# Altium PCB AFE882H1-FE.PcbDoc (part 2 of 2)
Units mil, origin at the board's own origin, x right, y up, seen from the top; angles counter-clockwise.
Board outline 2755.91 x 1181.1 mil, 4 copper layers (Top Layer, Int1 (GND), Int2 (PWR), Bottom Layer), stack 53.912 mil thick; 80 components, 47 nets, 216 pads, 76 vias.
Unrouted connection lines stored in the file: 4.
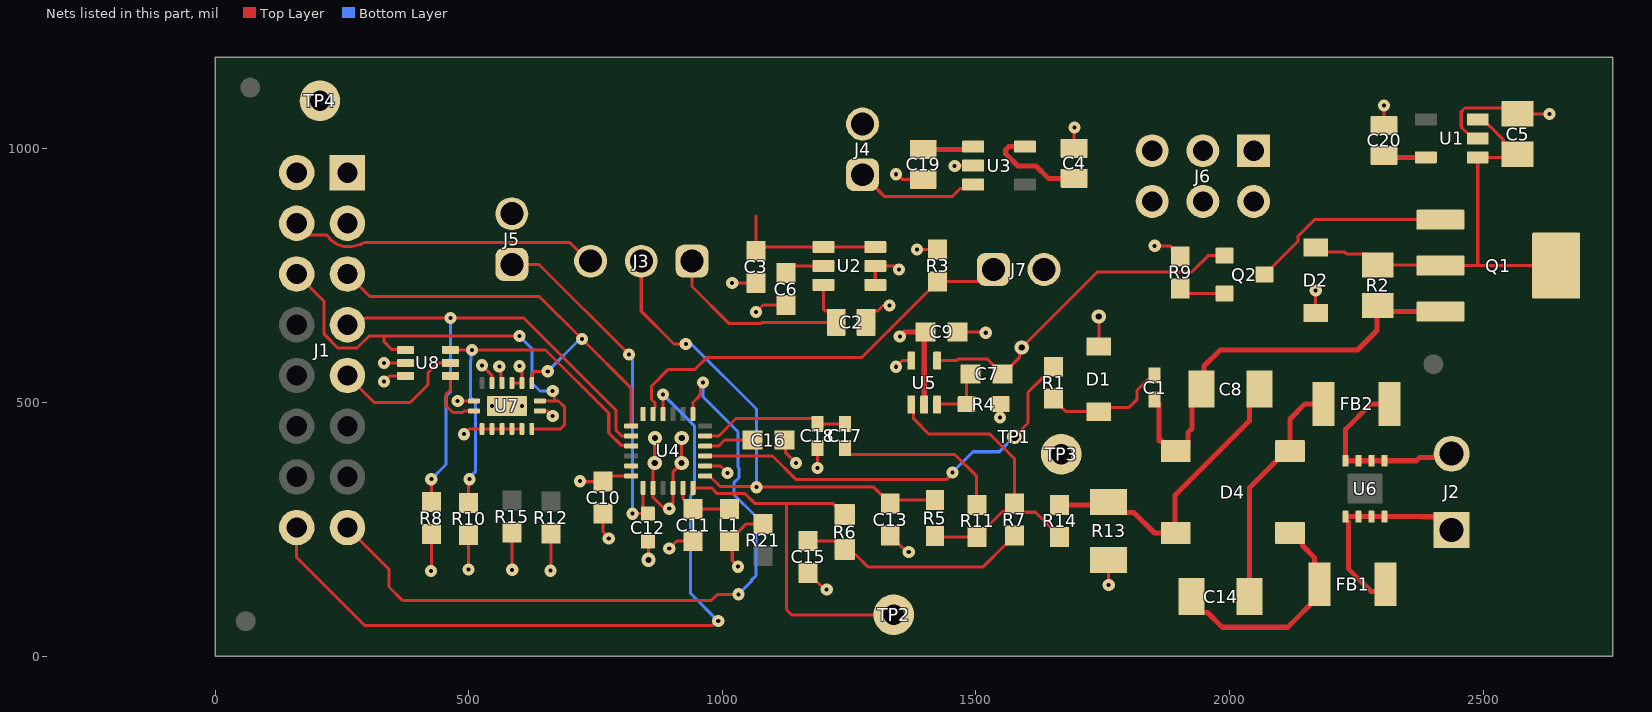
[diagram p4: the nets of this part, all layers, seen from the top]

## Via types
v1: diameter 24, hole 8, Top Layer to Bottom Layer, tented both sides, 63 vias
v2: diameter 28, hole 12, Top Layer to Bottom Layer, tented both sides, 7 vias
v3: diameter 19.68, hole 7.87, Top Layer to Bottom Layer, 4 vias
v4: diameter 19.68, hole 7.87, Top Layer to Bottom Layer, tented both sides, 2 vias

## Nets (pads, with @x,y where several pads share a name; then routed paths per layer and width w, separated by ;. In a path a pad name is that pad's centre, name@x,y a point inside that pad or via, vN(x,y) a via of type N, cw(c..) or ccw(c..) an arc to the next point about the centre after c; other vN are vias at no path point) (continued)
"DAC HART TX": J1.15 U4.1 | length 1410.4
  Top Layer w6: J1.15@260.52,253.39 342.59,171.33 342.59,136.14 368.77,109.96 978.48,109.96 990.38,121.85 v1(1031.83,121.85) ; U4.1@942.2,477.39 942.2,499.89 954.61,512.3 954.61,514.65 956.41,516.45 956.41,534.3 v1(961.88,539.77)
  Bottom Layer w6: v1(961.88,539.77) 961.88,511.25 1030.78,442.36 1030.78,372.71 1032.7,370.78 1032.7,351.83 1022.61,341.74 1022.61,318.68 1066.09,275.2 1066.09,158.55 1057.09,149.55 1057.09,147.11 v1(1031.83,121.85)
GND: C2.1 C3.2 C4.1 C5.2 C6.2 C9.2 C10.2 C11.2 C12.1 C13.2 C15.2 C16.1 C18.1 C19.1 C20.1 D2.2 J1.2 R3.2 R4.2 R9.1 R13.2 TP3.1 TP4.1 U1.2 U2.1 U2.2 U3.2 U4.14 U4.16 U4.20 U5.5 U7.3 U7.4 U7.6 U7.8 U7.10 U7.11 U7.12 U7.13 U7.14 U7.17 U8.3 | length 2085.8
  Top Layer w6: v1(332.92,541.68) 343.82,552.59 U8.3@375,552.59 ; v1(477.99,503.13) U7.8@510.04,503.13 ; v1(490.66,437.59) 501.07,448.01 U7.10@525.79,448.01 U7.11@545.47,448.01 U7.12@565.16,448.01 U7.13@584.84,448.01 U7.14@604.53,448.01 ; v1(525.79,573.39) 537.16,562.02 537.16,561.83 544.9,554.09 544.9,539.13 U7.6@545.47,538.56 ; U7.17@545.47,509.97 562.16,493.29 U7.17@575,493.29 U7.17@584.84,503.13 ; U7.4@584.84,538.56 U7.3@604.53,538.56 v1@604.46,571.3 ; C10.2@764.91,280.85 764.91,244.61 775.89,233.64 v1(775.89,232.1) ; C12.1@852.92,225.95 853.97,224.9 v2(853.97,189.87) v2@855.99,189.87 ; v2(866.93,430.19) 866.6,429.86 v2(866.6,381) 863.46,377.85 863.46,312.83 882.12,294.17 891.77,294.17 v1(895.22,290.73) 895.22,295.6 902.83,303.21 902.83,363.65 v2(919.7,380.52) 919.7,429.85 v2(919.74,429.89) ; v1(895.22,212.05) 910,226.84 C11.2@942.2,226.84 942.2,225.86 C11.2@957.9,210.15 ; U4.20@965.82,375.03 996.11,375.03 v1(1009.83,361.31) ; v1(1019.24,735.86) C3.2@1065.98,735.86 ; v1(1065.98,678.3) 1079.96,692.28 C6.2@1125.37,692.28 C6.2@1132.14,699.05 ; C16.1@1122.26,426.04 1124.17,424.13 1124.17,401.86 v1(1145.03,381) ; C15.2@1168.79,164.13 1168.79,163.14 1184.49,147.44 1185.48,147.44 1201.58,131.34 v1(1205.68,131.34) ; v1@1186.47,369.86 v1(1187.5,370.89) C18.1@1187.5,410.46 ; C2.1@1283.53,657.91 1283.53,664.61 1299.23,680.31 1305.92,680.31 1316.85,691.24 v1(1329.64,691.24) ; U2.1@1301.43,731.92 U2.2@1301.43,769.32 1341.31,769.32 v1(1348.29,762.34) ; C13.2@1332.65,235.9 C13.2@1330.98,237.58 1330.98,236.59 1346.68,220.89 1347.66,220.89 1363.03,205.52 v1(1367.46,205.52) ; v1(1342.11,570.58) 1354.12,582.6 U5.5@1372.38,582.6 ; v1(1342.11,950.15) 1344.65,950.15 1354.62,940.17 C19.1@1396.01,940.17 ; v1(1383.93,801.5) R3.2@1424.49,801.5 ; v1(1458.03,966.51) 1458.66,967.14 U3.2@1494.34,967.14 ; C9.2@1463.54,639.21 1517.77,639.21 v1(1519.31,637.67) ; v1(1547.33,470.35) 1548.64,471.66 R4.2@1548.64,496.91 ; C4.1@1693.54,1001.2 1693.54,1041.18 v1@1695.51,1043.14 ; v1(1761.77,140.07) R13.2@1761.77,189.77 ; v1(1852.46,809.07) 1882.06,809.07 1886.13,805.01 1887.11,805.01 1902.81,789.31 R9.1@1902.81,788.32 ; D2.2@2169.93,676.61 v1(2169.93,721.25) v1@2170.35,721.66 ; C20.1@2304.77,1046.4 v1(2304.77,1085.89) ; U1.2@2489.52,1020.88 2479.68,1020.88 2464.96,1035.6 2464.54,1035.6 2456.99,1043.14 2456.99,1073.42 2464.54,1080.97 2556.6,1080.97 C5.2@2568.24,1069.33 2630.65,1069.33 v1(2630.85,1069.12)
  other v1: 599.61,571.68 1694.52,1042.16
  other v4: 545.47,493.29 604.53,493.29
ID0: J1.6 U7.1 U7.15 U8.1 | length 949.6
  Top Layer w6: J1.6@160.52,753.39 214.65,699.27 214.65,634.39 241.52,607.52 279.53,607.52 303.34,631.33 332.92,631.33 ; U8.1@387.09,608.64 382.21,603.77 U8.1@375,603.77 374.59,604.18 348.42,604.18 332.92,619.68 332.92,631.33 ; v1(599.61,631.33) 332.92,631.33 ; U7.15@624.21,448.01 680.67,448.01 688.24,455.58 688.24,491.76 676.86,503.13 668.5,503.13 ; U7.1@639.96,503.13 668.5,503.13 ; v1(665.36,522.62) 668.5,519.47 668.5,503.13
  Bottom Layer w6: v1(599.61,631.33) 624.21,606.72 624.21,538.56 640.16,522.62 v1(665.36,522.62)
IOVDD: C10.1 J6.3 R8.2 R10.2 R12.2 R15.2 U4.12 U7.5 U7.16 U8.2 | length 494.8
  Top Layer w6: v1(332.85,578.25) 332.92,578.18 U8.2@375,578.18 ; v1@425.09,175.44 426.01,176.36 R8.2@426.01,240.53 ; v1(499.61,170.81) R10.2@499.61,239.18 ; v1(560.04,571.3) 563.43,567.9 563.43,540.29 U7.5@565.16,538.56 ; R15.2@584.84,243.67 584.84,170.81 v1(585.49,170.16) ; U7.16@639.96,483.44 640.42,482.99 655.6,482.99 v1(665.36,473.23) ; v1@660.41,167.84 661.65,169.08 R12.2@661.65,241.58 ; v1(719.09,344.93) 720.18,343.84 C10.1@764.91,343.84 776.41,355.34 U4.12@820.15,355.34
  other v1: 425.09,167.84 661.03,168.46
LOOP+: C1.2 C8.1 D4.1 Q1.3 R2.2 | length 871.4
  Top Layer w10: C1.2@1852.08,505.69 1858.41,499.36 1860.62,499.36 1860.62,424.62 1865.49,424.62 1886.1,404.01 1901.2,404.01 1917.86,420.66 1917.86,440.66 1925.98,448.78 1925.98,507.27 C8.1@1945.11,526.41 1949.71,531.01 1949.71,571.97 1981.51,603.78 2252.53,603.78 2290.8,642.05 2290.8,689.7 R2.2@2292.33,691.24 2304.12,679.45 Q1.3@2415.83,679.45
LOOP-: C8.2 D4.4 R13.1 R14.1 | length 610.4
  Top Layer w10: R14.1@1664.99,298.04 1755.87,298.04 R13.1@1761.77,303.95 1782.36,283.36 1811.23,283.36 1851.99,242.59 D4.4@1893.98,242.59 1892.4,244.16 1892.4,317.19 2039.37,464.17 2039.37,506.5 C8.2@2059.29,526.41
MOD_IN: R1.1 TP1.1 U4.21 | length 852.6
  Top Layer w6: U4.21@965.82,394.71 1098.97,394.71 1145.66,348.02 1441.32,348.02 1453.7,360.39 v1(1453.7,362.35) ; TP1.1@1568.72,432.57 TP1.1@1585.39,432.57 ; TP1.1@1577.06,434.08 1602.56,459.58 1602.56,520.07 1636.39,553.9 1637.37,553.9 1653.07,569.6 R1.1@1653.07,570.58
  Bottom Layer w6: v1(1453.7,362.35) 1494.35,403 1545.97,403 TP1.1@1577.06,434.08
NetC1_1: C1.1 D1.2 R1.2 | length 261
  Top Layer w6: R1.2@1653.07,507.59 1653.07,506.61 1677.54,482.13 1741.96,482.13 D1.2@1742.42,481.67 D1.2@1746.76,481.67 ; D1.2@1747.26,482.17 D1.2@1746.76,481.67 ; D1.2@1761.77,496.68 D1.2@1754.87,489.78 ; C1.1@1852.08,552.93 1845.74,546.6 1839.81,546.6 1817.92,524.72 1817.92,506.47 1801.24,489.78 D1.2@1754.87,489.78 ; D1.2@1746.76,481.67 D1.2@1754.87,489.78
NetC2_2: C2.2 J3.1 U2.6 | length 454
  Top Layer w6: J3.1@940,778.76 940,728.76 1013.33,655.43 1075.46,655.43 1077.94,657.91 C2.2@1224.47,657.91 1224.47,665.13 1208.77,680.83 1202.59,680.83 1199.07,684.34 U2.6@1199.07,731.92
NetC5_1: C5.1 D2.1 Q1.2 Q1.4 R2.1 U1.1 U1.3 | length 895
  Top Layer w6: D2.1@2169.93,805.55 2178.95,796.53 2227.4,796.53 2230.69,793.24 2270.33,793.24 R2.1@2292.33,771.24 2414.59,771.24 Q1.2@2415.83,770 2489.52,770 ; U1.3@2489.52,1058.28 2499.36,1058.28 2514.08,1043.57 2514.5,1043.57 2539.74,1018.33 2539.74,1011.33 2561.74,989.33 C5.1@2568.24,989.33 2562.4,983.48 U1.1@2489.52,983.48 2489.52,770 ; Q1.4@2644.17,770 2489.52,770
NetC6_1: C6.1 U2.5 | length 80.5
  Top Layer w6: C6.1@1125.37,754.29 C6.1@1125.37,755.27 1139.42,769.32 U2.5@1199.07,769.32
NetC7_1: C7.1 Q2.1 U5.4 | length 690.3
  Top Layer w6: U5.4@1423.56,582.6 1461.54,582.6 1465.2,586.26 1521.82,586.26 1551.4,556.69 C7.1@1552.38,556.69 1553.37,556.69 1586.11,589.43 1586.11,604.34 v2(1590.32,608.55) 1739.54,757.76 1926.02,757.76 1957.82,789.57 Q2.1@1990.16,789.57
  Bottom Layer w6: v2(1590.32,608.55) v2@1590.32,613.29
NetC7_2: C7.2 R4.1 U5.3 | length 121.5
  Top Layer w6: U5.3@1423.56,495.98 1424.49,496.91 R4.1@1481.71,496.91 1481.71,549 C7.2@1489.39,556.69
NetC11_1: C11.1 L1.1 U4.17 | length 121.8
  Top Layer w6: U4.17@922.51,331.72 922.51,310.03 926.03,306.52 926.5,306.52 942.09,290.92 942.09,289.94 C11.1@942.2,289.83 L1.1@1013.72,289.83
NetC14_1: C14.1 D4.3 FB1.1 | length 458.8
  Top Layer w10: C14.1@1925.2,117.43 1925.2,106.6 1945.79,86.01 1956.62,86.01 1985.8,56.82 2114.89,56.82 2120.75,62.68 2120.75,63.02 2170.35,112.62 FB1.1@2170.35,141.69 ; D4.3@2119.17,242.59 2127.05,242.59 2143.7,225.94 2143.7,218.06 2167.63,194.14 2167.63,151.82 FB1.1@2177.76,141.69
NetC14_2: C14.2 D4.2 FB2.1 | length 466.6
  Top Layer w10: C14.2@2039.37,117.43 2039.37,332.08 2111.3,404.01 D4.2@2119.17,404.01 2119.17,467.63 2148.94,497.39 FB2.1@2185.59,497.39
NetC15_1: C15.1 R6.1 R7.1 | length 463
  Top Layer w6: C15.1@1168.79,226.13 C15.1@1168.79,227.12 1225.09,227.12 1226.4,225.81 1228.6,225.81 1241.35,213.06 1241.35,211.09 1251.96,200.49 1262.59,200.49 1287.64,175.44 1513.53,175.44 1559.18,221.09 1560.17,221.09 1575.87,236.79 R7.1@1575.87,237.77 ; R6.1@1245.45,223.39 R6.1@1251.44,223.39
NetC16_2: C16.2 U4.22 | length 98.3
  Top Layer w6: U4.22@965.82,414.4 992.62,414.4 1004.27,426.04 C16.2@1059.26,426.04
NetC17_1: C17.1 R11.1 | length 342.2
  Top Layer w6: C17.1@1241.35,410.46 1241.35,406.52 1250.16,397.71 1458.03,397.71 1501.28,354.46 1501.28,298.95 R11.1@1502.18,298.04
NetC17_2: C17.2 C18.2 U4.23 | length 297.3
  Top Layer w6: U4.23@965.82,434.08 992.68,434.08 1026.97,468.37 1178.69,468.37 C18.2@1187.5,459.55 ; C18.2@1187.5,457.7 C17.2@1241.35,457.7 ; C18.2@1189.46,459.67 C18.2@1189.46,463.61
NetFB1_2: FB1.2 J2.1 U6.1 U6.2 U6.3 U6.4 | length 422.4
  Top Layer w10: FB1.2@2307.68,141.69 2293.7,127.7 2278.86,127.7 2234.21,172.35 2234.21,264 2228.94,269.27 U6.1@2228.94,274.98 U6.2@2254.53,274.98 U6.3@2280.12,274.98 2381.15,274.98 2381.36,274.77 2412.41,274.77 J2.1@2438.1,249.08
NetFB2_2: FB2.2 J2.2 U6.5 U6.6 U6.7 U6.8 | length 384.4
  Top Layer w10: FB2.2@2315.51,497.39 2278.86,497.39 2228.94,447.48 U6.8@2228.94,385.21 U6.7@2254.53,385.21 U6.6@2280.12,385.21 2368.48,385.21 2375.08,391.81 2430.83,391.81 J2.2@2438.1,399.08
NetJ4_1: J4.1 U3.3 | length 245.3
  Top Layer w6: J4.1@1276.3,949.23 1319.01,906.52 1453.7,906.52 1469.12,921.95 1486.55,921.95 U3.3@1494.34,929.74
NetQ1_1: Q1.1 Q2.3 | length 384.9
  Top Layer w6: Q2.3@2068.9,752.17 2070.87,752.17 2083.62,764.91 2083.62,766.88 2135.05,818.31 2135.05,828.06 2167.53,860.55 Q1.1@2402.05,860.55
NetQ2_2: Q2.2 R9.2 | length 91.7
  Top Layer w6: R9.2@1902.81,725.33 1913.38,714.77 Q2.2@1990.16,714.77
NetR5_2: R5.2 R7.2 R11.2 R14.2 U5.1 | length 651.7
  Top Layer w6: U5.1@1372.38,495.98 1377.26,491.11 1377.26,467.81 1407.47,437.59 1527.62,437.59 1575.87,389.35 R7.2@1575.87,300.77 ; R5.2@1419,236.59 1420.54,235.05 R11.2@1502.18,235.05 1502.18,236.04 1517.89,251.74 1518.87,251.74 1552.33,285.19 1560.3,285.19 R7.2@1575.87,300.77 ; R14.2@1664.99,236.03 1617.35,283.68 1592.96,283.68 1592.55,284.08 1591.57,284.08 1575.87,299.78 R7.2@1575.87,300.77
NetR6_2: R6.2 TP2.1 U4.18 | length 746.1
  Top Layer w6: U4.18@942.2,331.72 978.68,331.72 990.01,320.39 1044.71,320.39 1064.53,300.57 1126.38,300.57 ; R6.2@1241.35,279.07 1241.35,279.99 1228.6,292.74 1226.64,292.74 1218.81,300.57 1126.38,300.57 ; TP2.1@1337.73,81.48 1136.33,81.48 1126.38,91.43 1126.38,300.57
NetU4_6: U4.6
NetU4_11: U4.11
NetU7_9: U7.9 U8.4 | length 124.2
  Top Layer w6: U8.4@463.58,552.59 463.58,524.92 455.12,516.45 455.12,493.65 468.52,480.25 487.47,480.25 490.66,483.44 U7.9@510.04,483.44
PVDD: C9.1 D1.1 J6.4 J7.2 L1.2 R21.2 U5.2 | length 397.5
  Top Layer w6: v1(1030.79,176.36) 1019.39,187.75 1019.39,221.17 L1.2@1013.72,226.84 1013.72,227.82 1040.9,255 1046.22,260.31 R21.2@1080,260.31 ; R21.2@1085.35,253.46 R21.2@1086.11,252.7 ; v2(1742.09,669.8) 1742.42,669.46 D1.1@1742.42,610.61
  Top Layer w10: v1(1349.82,629.98) 1359.04,639.21 C9.1@1400.55,639.21 1397.97,636.64 U5.2@1397.97,495.98
REF_EN: J7.1 R3.1 U4.5 | length 829.3
  Top Layer w6: U4.5@863.46,477.39 863.46,486.25 867.35,490.14 867.35,499.04 860.27,506.12 860.27,532.29 893.35,565.37 946.1,565.37 970.01,589.27 1256.35,589.27 1275.26,589.27 1407.81,721.82 1408.79,721.82 1424.49,737.52 R3.1@1424.49,738.5 1503.31,738.5 1527.14,762.34 J7.1@1534.31,762.34
RTS: J1.16 U4.4 | length 1493.8
  Top Layer w6: J1.16@160.52,253.39 160.52,194.51 295.03,60 979.29,60 988.19,68.9 v1(991.81,68.9) ; U4.4@883.14,477.39 v1(883.14,515.59) v1@883.14,523.93
  Bottom Layer w6: v1(883.14,515.59) 944.61,454.12 944.61,323.2 937.34,315.92 937.34,123.37 v1(991.81,68.9)
SCLK: J1.5 U4.7 U7.2 | length 871.5
  Top Layer w6: J1.5@260.52,753.39 304.63,709.28 638.84,709.28 v1(722.99,625.13) 820.15,527.98 U4.7@820.15,453.77 ; U7.2@624.21,538.56 624.21,555.03 630.83,561.65 v1(655.6,561.65)
  Bottom Layer w6: v1(655.6,561.65) 719.09,625.13 v1(722.99,625.13)
SDI: J1.7 R8.1 U4.8 | length 1063
  Top Layer w6: J1.7@260.52,653.39 272.77,665.64 295.2,665.64 296.04,666.48 v1(463.58,666.48) 608.55,666.48 789.76,485.26 789.76,445.74 801.43,434.08 U4.8@820.15,434.08 ; R8.1@426.01,303.52 v1(426.01,348.85)
  Bottom Layer w6: v1(426.01,348.85) 455.12,377.95 455.12,512.6 463.58,521.07 v1(463.58,666.48)
SDO: J1.9 U8.5 | length 271
  Top Layer w6: J1.9@260.52,553.39 313.64,500.27 384.38,500.27 419.29,535.18 419.29,558.49 438.97,578.18 U8.5@463.58,578.18
SDO_DAC: R10.1 U4.9 U8.6 | length 771.1
  Top Layer w6: U8.6@463.58,603.77 v1(506.3,603.77) 651.3,603.77 775.89,479.18 775.89,440 800.29,415.59 818.95,415.59 U4.9@820.15,414.4 ; R10.1@499.61,302.17 499.61,347.38 v1(501.07,348.85)
  Bottom Layer w6: v1(501.07,348.85) 501.07,352.24 513.53,364.7 513.53,500.19 502.91,510.8 502.91,582.87 504.13,584.09 504.13,601.6 v1(506.3,603.77)
VDD-1V8: C3.1 C4.2 J1.3 J5.2 J6.5 J6.6 U2.3 U2.4 U3.5 | length 510.9
  Top Layer w6: 1065.98,867.6 C3.1@1065.98,798.85 1073.86,806.73 U2.4@1199.07,806.73 U2.3@1301.43,806.73
  Top Layer w10: U3.5@1596.7,1004.54 1564.59,1004.54 1558.74,998.68 1558.74,990.4 1582.87,966.27 1618.5,966.27 1642.63,942.14 C4.2@1693.54,942.14
VDD-3V3: C19.2 C20.2 J1.1 J4.2 J6.1 J6.2 U1.5 U3.1 | length 184.5
  Top Layer w10: C19.2@1396.01,999.23 1489.03,999.23 U3.1@1494.34,1004.54 ; C20.2@2304.77,987.35 2308.64,983.48 U1.5@2387.16,983.48
VDD_int: C12.2 J5.1 U4.13 | length 705.7
  Top Layer w6: J5.1@584.69,772.34 638.36,772.34 v1@817.01,593.68 ; v1(822.41,280.85) 852.7,280.85 C12.2@852.92,281.07 ; C12.2@842.14,290.07 849.76,282.45 C12.2@849.76,281.07 ; C12.2@843.77,290.22 U4.13@843.77,331.72
  Bottom Layer w6: v1@817.01,593.68 822.41,588.29 v1(822.41,280.85)
  other v1: 815.95,594.74
VREF: J1.4 J3.3 | length 613.6
  Top Layer w6: J1.4@160.52,853.39 183.76,830.16 220.16,830.16 221.91,828.4 ccw(c260.43,853.33) 260.43,807.45 ccw(c260.43,884.24) 295.03,815.69 698.69,815.69 735.62,778.76 J3.3@740,778.76
VREFIO: C13.1 J3.2 R5.1 U4.19 | length 1039.5
  Top Layer w6: J3.2@840,778.76 840,680.29 904.7,615.59 v1(927.85,615.59) ; U4.19@965.82,355.34 974.68,355.34 995.75,334.26 1065.91,334.26 v1(1067.13,333.05) 1298.49,333.06 1314.29,317.26 1315.28,317.26 1334.42,298.11 C13.1@1334.42,297.13 ; C13.1@1336.15,298.85 1344.76,307.46 R5.1@1419,307.46
  Bottom Layer w6: v1(927.85,615.59) 938.77,615.59 1067.13,487.23 v1(1067.13,333.05)
pads on no net: FID1.1 FID2.1 FID3.1 J1.8 J1.10 LBL1.0 SH-J1.0 SH-J2.0 SH-J3.0 SH-J4.0 SH-J5.0 U1.4 U3.4 U6.9 U7.7
copper on no net:
  other v3: 2267.33,310.41 2242.72,330.1 2291.93,330.1 2267.33,349.78

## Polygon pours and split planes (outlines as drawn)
VDD-3V3 on Top Layer "TOP_LAYER_VDD-3V3_P021" (solid, remove dead copper, pour order 21): 1956.17,1042.16 1997.52,1000.81 1997.52,870.88 2021.89,846.51 2071.69,846.51 2097.52,872.34 2097.52,946.51 2256.2,946.51 2292.33,982.64 2333.31,982.64 2333.31,1016.88 2213.31,1136.88 2200.4,1137.9 375.98,1144.89 220,988.91 220,916.95 300,916.95 365.69,982.64 1443.04,982.64 1450.74,990.34 1450.74,1029.87 1463.03,1042.16
VDD-1V8 on Top Layer "TOP_LAYER_VDD-1V8_P022" (solid, remove dead copper, pour order 22): 1781.46,951.51 1805.04,975.09 1805.04,1010.01 1831.12,1036.1 1868.01,1036.1 1888.85,1015.26 1888.85,870.44 1860.87,842.46 405.28,842.46 380.68,817.86 220,817.86 220,886.94 220.12,886.82 342.59,886.82 407.28,951.51 1226.3,951.51 1226.3,904.69 1241.39,889.6 1649.55,889.6 1677.54,917.59 1677.54,951.51
PVDD on Int2 (PWR) "INT2_(PWR)_PVDD_P024" (solid, remove dead copper, pour order 24): 1917.86,901.1 1917.86,832.11 1887.11,801.36 1886.66,801.8 1520.33,801.8 1489.23,770.7 1400.97,682.45 1360.48,682.45 998.18,320.15 998.18,167.74 1007.37,158.55 1075.52,158.55 1553.62,636.64 1849.48,636.64 1982.52,773.29 1982.52,914.39 1963.92,932.99 1939.07,932.99 1917.86,911.78
IOVDD on Int2 (PWR) "INT2_(PWR)_IOVDD_P025" (solid, remove dead copper, pour order 25): 1915.36,971.67 1923.27,963.76 1973.01,963.76 1991.89,982.64 1990.16,984.37 1990.16,1069.12 1948.29,1110.99 744.53,1110.99 463.58,830.04 463.58,631.33 550.65,631.33 562.29,619.68 579.43,636.82 579.43,830.52 725.43,976.51 1915.36,976.51
IOVDD on Int2 (PWR) "INT2_(PWR)_IOVDD_P023" (solid, remove dead copper, pour order 23): 310.52,603.39 352.25,645.12 681.39,645.12 750,576.51 750,199.88 682.79,132.68 381.24,132.68 310.52,203.39
GND on Int1 (GND) "INT1_(GND)_GND_P002" (solid, remove dead copper, pour order 2): 0,1181.1 0,0 2755.91,0 2755.91,1181.1

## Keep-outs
Keep-Out Layer:
  text ".Layer_Name" at 577,-858.49 h60

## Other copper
Top Layer:
  text ".Layer_Name" at 577,-858.49 h60
Bottom Layer:
  text ".Layer_Name" at 577,-858.49 h60

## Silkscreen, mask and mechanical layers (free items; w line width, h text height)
Top Overlay:
  text "IOVDD" at 1871.49,1119.82 h30
  text "PVDD" at 1883.82,1063.84 h30
  text "FT_EVP_AFE88_E1" at 354.92,1045.85 h60
  text "1.8_En" at 1199.69,915.42 h30 r90
  text "3.3V" at 2120.89,878.34 h30
  text "Vref" at 806.29,858.94 h30
  text "1.8V" at 1678.52,852.51 h30
  text "ref_EN" at 1498.03,823.01 h30
  text "VDD_int" at 514.79,734.76 h30 r90
  text ".Layer_Name" at 577,-858.49 h60
Bottom Overlay:
  text ".Layer_Name" at 577,-858.49 h60
Top Paste:
  text ".Layer_Name" at 577,-858.49 h60
Bottom Paste:
  text ".Layer_Name" at 577,-858.49 h60
Top Solder:
  text ".Layer_Name" at 577,-858.49 h60
  text ".Layer_Name" at 577,-858.49 h60
Bottom Solder:
  text ".Layer_Name" at 577,-858.49 h60
Drill Guide:
  text ".Layer_Name" at 577,-858.49 h60
M1 Board Outline:
  the board outline again, w7
  text ".Layer_Name" at 577,-858.49 h60
M2 Board Dimensions:
  rectangle: 0,-275 125,-150
  rectangle: 125,-400 500,-275
  lines w7: 0,-275 1000,-275 ; 125,-400 125,-150 ; 250,-400 250,-150 ; 500,-400 500,-150 ; 750,-400 750,-150 ; 0,-400 1000,-400 1000,-150 0,-150 0,-400
  text ".Layer_Name" at 577,-858.49 h60
M3 3D STEP Top:
  text ".Layer_Name" at 577,-858.49 h60
M4 3D STEP Bottom:
  text ".Layer_Name" at 577,-858.49 h60
M5 Assembly Top:
  lines w10: -292,-930.17 6308,-930.17 ; -292,-726.83 6310,-726.83 ; -292,-523.5 -292,-1133.5 3713,-1133.5 6310,-1133.5 6310,-523.5 -291.5,-523.5 -291.5,-1133.5 1284,-1133.5 ; 2173,-1133.5 2173,-523.5 ; 3440,-726.83 3440,-523.5 ; 4280,-726.83 4280,-523.5 ; 4902,-1140 4902,-937.17
  text "COMPONENTS MARKED 'DNP' SHOULD NOT BE POPULATED." at 1153.5,-318.5 h60
  text "ASSEMBLY VARIANT:" at 1153,-434 h60
  text ".VariantName" at 2189,-434 h60
  text "PCB VIEWED FROM TOP SIDE" at -228.5,-655.67 h60
  text "BOARD #:" at 2248,-655.67 h60
  text ".PRJ_Number" at 2793.5,-655.67 h60
  text "REV:" at 3638,-655.67 h60
  text ".PCB_Rev" at 3929.5,-655.67 h60
  text "SVN REV:" at 4476,-655.67 h60
  text ".VersionControl_RevNumber" at 4982,-655.67 h60
  text "TID #:" at 2248,-859 h60
  text ".TID" at 2793.5,-859 h60
  text "PLOT NAME =" at -228.5,-1064.34 h60
  text ".plot_File_Name" at 577,-1064.34 h60
  text "GENERATED    :" at 2250,-1064.34 h60
  text ".Print_Date" at 3119.5,-1064.34 h60
  text ".Print_Time" at 3848.5,-1064.34 h60
  text "TEXAS INSTRUMENTS" at 5113,-1064.34 h60
M6 Assembly Bottom:
  lines w10: -292.5,-727.33 6309.5,-727.33 ; -290.5,-930.67 6309.5,-930.67 ; 1115.5,-1140.5 1115.5,-937.67 ; 1737.5,-727.33 1737.5,-524 ; 2577.5,-727.33 2577.5,-524 ; 3844.5,-1134 3844.5,-524 ; 4733.5,-1134 6309,-1134 6309,-524 -292.5,-524 -292.5,-1134 2304.5,-1134 6309.5,-1134 6309.5,-524
  text "COMPONENTS MARKED 'DNP' SHOULD NOT BE POPULATED." at 6102,-318 h60
  text ".VariantName" at 5058,-434 h60
  text "ASSEMBLY VARIANT:" at 6097,-434 h60
  text ".VersionControl_RevNumber" at 1035.5,-656.17 h60
  text "SVN REV:" at 1541.5,-656.17 h60
  text ".PCB_Rev" at 2088,-656.17 h60
  text "REV:" at 2379.5,-656.17 h60
  text ".PRJ_Number" at 3224,-656.17 h60
  text "BOARD #:" at 3769.5,-656.17 h60
  text "PCB VIEWED FROM BOTTOM SIDE" at 6246,-656.17 h60
  text ".TID" at 3224,-859.5 h60
  text "TID #:" at 3769.5,-859.5 h60
  text "TEXAS INSTRUMENTS" at 904.5,-1064.84 h60
  text ".Print_Time" at 2169,-1064.84 h60
  text ".Print_Date" at 2898,-1064.84 h60
  text "GENERATED    :" at 3767.5,-1064.84 h60
  text ".plot_File_Name" at 5440.5,-1064.84 h60
  text "PLOT NAME =" at 6246,-1064.84 h60
M9 Title Sheet:
  drawing of 57 lines, arcs and shapes, not listed
  text "1" at 739.84,8036.5 h70
  text "2" at 3235.5,8036.5 h70
  text "3" at 5724.84,8036.5 h70
  text "4" at 8231.51,8036.5 h70
  text "5" at 10730.5,8036.5 h70
  text "6" at 13235.5,8036.5 h70
  text "A" at -416.5,6893.5 h70
  text "A" at 14383.5,6893.5 h70
  text "B" at -416.5,4513.5 h70
  text "B" at 14383.5,4513.5 h70
  text "C" at -416.5,2138.5 h70
  text "C" at 14383.5,2138.5 h70
  text "PROJECT TITLE:" at 11343.5,277.5 h45
  text ".PRJ_Title" at 11393.5,144.17 h70
  text "DESIGNED FOR:" at 11343.5,-23.5 h45
  text ".PRJ_Customer" at 11393.5,-163.5 h70
  text "D" at -416.5,-231.5 h70
  text "D" at 14383.5,-231.5 h70
  text "FILE NAME:" at 11343.5,-323.5 h45
  text ".PCB_File_Name_No_Path" at 11393.5,-443.5 h70
  text "Texas Instruments (TI) and/or its licensors do not warrant the accuracy or completeness of this specification" at 6374,-605.34 h45
  text "ENGINEER:" at 11343.5,-613.5 h45
  text "LAYOUT BY:" at 12848.5,-613.5 h45
  text "or any information contained therein. TI and/or its licensors do not warrant that this design will meet" at 6329.01,-718 h45
  text ".PRJ_Engineer" at 11393.5,-768.49 h70
  text ".PCB_Layout" at 12899,-768.49 h70
  text "the specifications, will be suitable for your application or fit for any particular purpose, or will operate in" at 6329.01,-830.67 h45
  text ".Layer_Name" at 577,-858.49 h60
  text "ALTIUM DESIGNER VERSION:" at 12848.5,-923.5 h45
  text "an implementation. TI and/or its licensors do not warrant that the design is production worthy. You should" at 6329.01,-943.33 h45
  text "completely validate and test your design implementation to confirm the system functionality for your application." at 6374,-1056 h45
  text ".print_Scale" at 11393.5,-1056.83 h70
  text ".Application_BuildNumber" at 12899,-1056.83 h70
  text "1" at 739.84,-1263.5 h70
  text "2" at 3235.5,-1263.5 h70
  text "3" at 5724.84,-1263.5 h70
  text "4" at 8231.51,-1263.5 h70
  text "5" at 10730.5,-1263.5 h70
  text "6" at 13235.5,-1263.5 h70
M10 Fab Notes:
  drawing of 187 lines, arcs and shapes, not listed
  text "DESIGN INFORMATION" at 12382.02,6356.17 h60
  text "MIN. TRACK WIDTH:" at 11737.46,6224.05 h60
  text "8" at 12833.7,6224.05 h60
  text "MIL" at 12988.46,6224.05 h60
  text "7.874" at 12667.32,6102.36 h60
  text "MIN. CLEARANCE:" at 11737.46,6099.92 h60
  text "MIL" at 12988.46,6099.92 h60
  text "MIN. VIA PAD SIZE:" at 11737.46,5975.8 h60
  text "24" at 12803.71,5975.8 h60
  text "MIL" at 12988.46,5975.8 h60
  text "0.05mm (2MIL)" at 12432.46,5845.9 h60
  text "MINIMUM ANNULAR RING" at 11408.23,5837.67 h60
  text "EXTERNAL" at 13140.46,5837.67 h60
  text "PER" at 11608.23,5727.55 h60
  text "IPC-D-275 CLASS 2 LEVEL C" at 11828.23,5727.54 h60
  text "MIL, HOLES" at 13316.46,5627.07 h60
  text "+/-" at 12924,5618.48 h60
  text "+/-" at 13778,5618.48 h60
  text "REGISTRATION TOLERANCES:" at 11408.23,5617.42 h60
  text "METAL" at 12608,5617.42 h60
  text "5" at 13184.2,5617.42 h60
  text "3" at 14017.2,5617.42 h60
  text "MIL" at 14133.46,5617.42 h60
  text "HOLE SIZE TOLERANCE (UNLESS OTHERWISE SPECIFIED):" at 11408.23,5519.1 h60
  text "+/-" at 13778,5516.23 h60
  text "3" at 14017.2,5515.17 h60
  text "MIL" at 14133.46,5515.17 h60
  text "MATERIAL:" at 11333.46,5377.52 h60
  text "FR-4 High Tg" at 12319.9,5249 h60
  text "X" at 12175.46,5241.01 h60
  text "FR-4" at 11754.46,5236.49 h60
  text "OTHER" at 13242.46,5236.49 h60
  text "62 MIL (1.6mm) +/-10%" at 12074.56,5093.46 h60
  text "X" at 11954.46,5091.01 h60
  text "THICKNESS:" at 11408.23,5085.24 h60
  text "OTHER" at 13359.46,5085.24 h60
  text "TOLERANCE:" at 11408.23,4946.92 h60
  text "X" at 12256.46,4946.92 h60
  text "ANSI IPC-6012 TYPE 3 CLASS 2" at 12434.48,4946.92 h60
  text "OTHER +/-" at 12434.46,4802.73 h60
  text "BOW & TWIST:" at 11408.23,4657.54 h60
  text "X" at 12256.46,4657.54 h60
  text "ANSI IPC-6012 TYPE 3 CLASS 2" at 12434.48,4657.54 h60
  text "OTHER +/-" at 12434.46,4510.85 h60
  text "DRILLING:" at 11333.46,4380.23 h60
  text "NC_DRILL FILES" at 13094.46,4275.04 h60
  text "REFERENCE:" at 11408.23,4271.1 h60
  text "X" at 12065.46,4271.01 h60
  text "AS SHOWN" at 12243.46,4271.1 h60
  text "X" at 12966.46,4271.1 h60
  text "OTHER" at 13392.46,4128.85 h60
  text "PTH COPPER THICKNESS:" at 11407.91,4125.32 h60
  text "X" at 12547.14,4125.32 h60
  text "20-30 um" at 12675.14,4125.32 h60
  text "BOARD FINISH:" at 11333.46,3977.73 h60
  text "SILKSCREEN:" at 11488.68,3867.6 h60
  text "X" at 12446.46,3867.6 h60
  text "TOP" at 12563.46,3867.6 h60
  text "X" at 12956.46,3867.6 h60
  text "BOTTOM" at 13074.46,3867.6 h60
  text "SILKSCREEN COLOR:" at 11488.68,3712.41 h60
  text "X" at 12445.46,3712.41 h60
  text "WHITE" at 12563.46,3712.41 h60
  text "OTHER" at 13074.46,3712.41 h60
  text "X" at 12576.46,3568.96 h60
  text "GREEN" at 12694.46,3568.96 h60
  text "OTHER" at 13312.46,3568.96 h60
  text "SOLDER RESIST COLOR:" at 11488.68,3562.1 h60
  text "X" at 12576.46,3414.71 h60
  text "MATTE" at 12694.46,3414.71 h60
  text "SEMI-GLOSS" at 13312,3414.07 h60
  text "IMMERSION GOLD (ENIG)" at 12394.46,3241.94 h60
  text "ENEPIG" at 13732,3234.72 h60
  text "SURFACE FINISH:" at 11333.46,3233.72 h60
  text "X" at 12216.46,3233.72 h60
  text "IMM. TIN/SILVER OR EQUIV" at 11663,3096.4 h60
  text "OTHER" at 13094.46,3092.47 h60
  text "ARRAY/PANEL:" at 11333.46,2937.09 h60
  text "CUT AND TRIM PER M1 BOARD OUTLINE" at 12394.46,2928.87 h60
  text "N.C. ROUTE" at 12394.46,2792.9 h60
  text "X" at 13082.46,2792.9 h60
  text "V. SCORE" at 13260.46,2792.9 h60
  text "CERTIFICATION:" at 11333.46,2663.77 h60
  text "MATERIALS AND WORKMANSHIP FOR ALL PCBS" at 12058.46,2663.77 h60
  text "TO MEET OR EXCEED THE REQUIREMENTS OF:" at 12058.46,2569.71 h60
  text "X" at 11695.97,2441.08 h60
  text "ANSI IPC-A-600F CLASS ->" at 11823.96,2441.08 h60
  text "X" at 13471.97,2441.08 h60
  text "2" at 13581.96,2441.08 h60
  text "1" at 13266.96,2439.58 h60
  text "3" at 13935.96,2439.58 h60
  text "X" at 12507.97,2293.39 h60
  text "RoHS" at 12635.96,2293.39 h60
  text "OTHER" at 13280.36,2293.39 h60
  text "PER ORDER" at 13677.42,2293.39 h60
  text "ALL BOARDS MUST MEET OR EXCEED UL94-V0 REQUIREMENTS." at 11361,2139.57 h60
  text "PCB MUST BEAR THE UL94V-0 UL REGISTERED MATERIAL ID NUMBER" at 11361,2023.5 h60
  text "ADDITIONAL REQUIREMENTS:" at 11333.46,1854.08 h60
  text "MICROSECTION:" at 11408.23,1746.95 h60
  text "YES" at 12313.96,1746.95 h60
  text "REQUIRED" at 13175.46,1602.62 h60
  text "BARE BOARD ELEC. TEST:" at 11408.23,1599.76 h60
  text "NONE" at 12713.96,1599.76 h60
  text "X" at 13057.46,1599.76 h60
  text "PER ORDER" at 13767.46,1599.76 h60
  text "XX MIL VIAS REQUIRE NON-CONDUCTIVE FILL AND PLANARIZE" at 11576.38,1394.82 h59
  text "XX MIL VIAS REQUIRE CONDUCTIVE FILL AND PLANARIZE" at 11584.38,1290.84 h60
  text "OUTER XX MIL TRACES REQUIRE 50 OHM SINGLE-ENDED IMPEDANCE" at 11583.39,1127.46 h58
  text "LAYER 2 & 3 (INNER LAYERS) XX MIL WIDE, XX MIL SPACE / TRACES REQUIRE 100 OHM DIFFERENTIAL IMPEDANCE" at 11575.39,891.74 h60
  text ".Layer_Name" at 577,-858.49 h60
M11 Gerber Information:
  lines w10: -292,-930.17 6308,-930.17 ; -292,-726.83 6310,-726.83 ; -292,-523.5 -292,-1133.5 3713,-1133.5 6310,-1133.5 6310,-523.5 -291.5,-523.5 -291.5,-1133.5 1284,-1133.5 ; 2173,-1133.5 2173,-523.5 ; 3440,-726.83 3440,-523.5 ; 4280,-726.83 4280,-523.5 ; 4902,-1140 4902,-937.17
  text "ALL ARTWORK VIEWED FROM TOP SIDE" at -228.5,-655.67 h60
  text "BOARD #:" at 2248,-655.67 h60
  text ".PRJ_Number" at 2793.5,-655.67 h60
  text "REV:" at 3638,-655.67 h60
  text ".PCB_Rev" at 3929.5,-655.67 h60
  text "SVN REV:" at 4476,-655.67 h60
  text ".VersionControl_RevNumber" at 4982,-655.67 h60
  text "LAYER NAME =" at -228.5,-858.49 h60
  text "TID #:" at 2248,-859 h60
  text ".TID" at 2793.5,-859 h60
  text "PLOT NAME =" at -228.5,-1064.34 h60
  text ".plot_File_Name" at 577,-1064.34 h60
  text "GENERATED    :" at 2250,-1064.34 h60
  text ".Print_Date" at 3119.5,-1064.34 h60
  text ".Print_Time" at 3848.5,-1064.34 h60
  text "TEXAS INSTRUMENTS" at 5113,-1064.34 h60
M12 Stackup:
  drawing of 399 lines, arcs and shapes, not listed
  text "Layer" at 9821.59,7874.94 h60
  text "Name" at 10231.51,7874.94 h60
  text "Material" at 11561.12,7874.94 h60
  text "Thickness" at 12160.97,7874.94 h60
  text "Constant" at 12810.81,7874.94 h60
  text "Board Layer Stack" at 13380.67,7874.94 h60
  text "Top Overlay" at 10231.51,7754.94 h60
  text "Top Solder" at 10231.51,7634.94 h60
  text "SM-001" at 11561.12,7634.94 h60
  text "1.00mil" at 12160.97,7634.94 h60
  text "4" at 12810.81,7634.94 h60
  text "Top Surface Finish" at 10231.51,7514.94 h60
  text "PbSn" at 11561.12,7514.94 h60
  text "0.79mil" at 12160.97,7514.94 h60
  text "1" at 9821.59,7394.94 h60
  text "Top Layer" at 10231.51,7394.94 h60
  text "CF-004" at 11561.12,7394.94 h60
  text "1.38mil" at 12160.97,7394.94 h60
  text "Dielectric 1" at 10231.51,7274.94 h60
  text "PP-017" at 11561.12,7274.94 h60
  text "5.10mil" at 12160.97,7274.94 h60
  text "4.3" at 12810.81,7274.94 h60
  text "Dielectric 2" at 10231.51,7154.94 h60
  text "PP-017" at 11561.12,7154.94 h60
  text "5.10mil" at 12160.97,7154.94 h60
  text "4.3" at 12810.81,7154.94 h60
  text "2" at 9821.59,7034.94 h60
  text "Int1 (GND)" at 10231.51,7034.94 h60
  text "CF-004" at 11561.12,7034.94 h60
  text "1.38mil" at 12160.97,7034.94 h60
  text "Dielectric 3" at 10231.51,6914.94 h60
  text "Core-039" at 11561.12,6914.94 h60
  text "28.00mil" at 12160.97,6914.94 h60
  text "4.8" at 12810.81,6914.94 h60
  text "3" at 9821.59,6794.94 h60
  text "Int2 (PWR)" at 10231.51,6794.94 h60
  text "CF-004" at 11561.12,6794.94 h60
  text "1.38mil" at 12160.97,6794.94 h60
  text "Dielectric 4" at 10231.51,6674.94 h60
  text "PP-017" at 11561.12,6674.94 h60
  text "5.10mil" at 12160.97,6674.94 h60
  text "4.3" at 12810.81,6674.94 h60
  text "Dielectric 5" at 10231.51,6554.94 h60
  text "PP-017" at 11561.12,6554.94 h60
  text "5.10mil" at 12160.97,6554.94 h60
  text "4.3" at 12810.81,6554.94 h60
  text "4" at 9821.59,6434.94 h60
  text "Bottom Layer" at 10231.51,6434.94 h60
  text "CF-004" at 11561.12,6434.94 h60
  text "1.38mil" at 12160.97,6434.94 h60
  text "Bottom Surface Finish" at 10231.51,6314.94 h60
  text "PbSn" at 11561.12,6314.94 h60
  text "0.79mil" at 12160.97,6314.94 h60
  text "Bottom Solder" at 10231.51,6194.94 h60
  text "SM-001" at 11561.12,6194.94 h60
  text "1.00mil" at 12160.97,6194.94 h60
  text "4" at 12810.81,6194.94 h60
  text "Bottom Overlay" at 10231.51,6074.94 h60
  text ".Layer_Name" at 577,-858.49 h60
M13 Component Bodies Top:
  text ".Layer_Name" at 577,-858.49 h60
M14 Component Bodies Bottom:
  text ".Layer_Name" at 577,-858.49 h60
M15 Courtyards Top:
  text ".Layer_Name" at 577,-858.49 h60
M16 Courtyards Bottom:
  text ".Layer_Name" at 577,-858.49 h60
Drill Drawing:
  circle w10: c5363.63,3042.14 r27.59
  lines w10: 5336.04,2573.03 5391.23,2573.03 5363.63,2517.84 5336.04,2573.03 ; 5336.04,2642.02 5363.63,2655.82 5391.23,2642.02 5377.43,2669.62 5391.23,2697.21 5363.63,2683.41 5336.04,2697.21 5349.83,2669.62 5336.04,2642.02 ; 5336.04,2766.2 5391.23,2766.2 5391.23,2821.39 5336.04,2821.39 5336.04,2766.2 ; 5336.04,2890.37 5336.04,2904.17 5349.83,2917.97 5336.04,2931.76 5336.04,2945.56 5349.83,2945.56 5363.63,2931.76 5377.43,2945.56 5391.23,2945.56 5391.23,2931.76 5377.43,2917.97 5391.23,2904.17 5391.23,2890.37 5377.43,2890.37 5363.63,2904.17 5349.83,2890.37 5336.04,2890.37 ; 5336.04,3152.52 5349.83,3152.52 5349.83,3138.72 5377.43,3138.72 5377.43,3152.52 5391.23,3152.52 5391.23,3180.12 5377.43,3180.12 5377.43,3193.91 5349.83,3193.91 5349.83,3180.12 5336.04,3180.12 5336.04,3152.52 ; 5336.04,3276.7 5349.83,3276.7 5363.63,3262.9 5377.43,3276.7 5391.23,3276.7 5377.43,3290.5 5391.23,3304.29 5377.43,3304.29 5363.63,3318.09 5349.83,3304.29 5336.04,3304.29 5349.83,3290.5 5336.04,3276.7
  lines w12: 5286,2480.59 8516.52,2480.59 ; 5286,3349.82 8516.52,3349.82 ; 5623.86,2356.42 5623.86,3474 ; 5955.86,2356.42 5955.86,3474 ; 6592.42,2356.42 6592.42,3474 ; 6851.53,2356.42 6851.53,3474 ; 7226.68,2356.42 7226.68,3474 ; 7950.06,2356.42 7950.06,3474 ; 5286,2356.42 8516.52,2356.42 8516.52,3474 5286,3474 5286,2356.42
  text "Symbol" at 5360.51,3387.08 h72
  text "Quantity" at 5661.11,3387.08 h72
  text "Finished Hole Size" at 5993.12,3387.08 h72
  text "Plated" at 6629.67,3387.08 h72
  text "Hole Type" at 6888.78,3387.08 h72
  text "Drill Layer Pair" at 7263.93,3387.08 h72
  text "Hole Tolerance" at 7987.32,3387.08 h72
  text "6" at 5661.11,3262.9 h60
  text "7.87mil (0.200mm)" at 5993.12,3262.9 h60
  text "PTH" at 6629.67,3262.9 h60
  text "Round" at 6888.78,3262.9 h60
  text "Top Layer - Bottom Layer" at 7263.93,3262.9 h60
  text "63" at 5661.11,3138.72 h60
  text "8.00mil (0.203mm)" at 5993.12,3138.72 h60
  text "PTH" at 6629.67,3138.72 h60
  text "Round" at 6888.78,3138.72 h60
  text "Top Layer - Bottom Layer" at 7263.93,3138.72 h60
  text "7" at 5661.11,3014.55 h60
  text "12.00mil (0.305mm)" at 5993.12,3014.55 h60
  text "PTH" at 6629.67,3014.55 h60
  text "Round" at 6888.78,3014.55 h60
  text "Top Layer - Bottom Layer" at 7263.93,3014.55 h60
  text "1" at 5661.11,2890.37 h60
  text "17.72mil (0.450mm)" at 5993.12,2890.37 h60
  text "PTH" at 6629.67,2890.37 h60
  text "Round" at 6888.78,2890.37 h60
  text "Top Layer - Bottom Layer" at 7263.93,2890.37 h60
  text "25" at 5661.11,2766.2 h60
  text "40.00mil (1.016mm)" at 5993.12,2766.2 h60
  text "PTH" at 6629.67,2766.2 h60
  text "Round" at 6888.78,2766.2 h60
  text "Top Layer - Bottom Layer" at 7263.93,2766.2 h60
  text "9" at 5661.11,2642.02 h60
  text "45.28mil (1.150mm)" at 5993.12,2642.02 h60
  text "PTH" at 6629.67,2642.02 h60
  text "Round" at 6888.78,2642.02 h60
  text "Top Layer - Bottom Layer" at 7263.93,2642.02 h60
  text "2" at 5661.11,2517.84 h60
  text "47.24mil (1.200mm)" at 5993.12,2517.84 h60
  text "PTH" at 6629.67,2517.84 h60
  text "Round" at 6888.78,2517.84 h60
  text "Top Layer - Bottom Layer" at 7263.93,2517.84 h60
  text "113 Total" at 5661.11,2393.67 h60
  text ".Layer_Name" at 577,-858.49 h60
M17 Embedded Cavity:
  text ".Layer_Name" at 577,-858.49 h60
M18 Embedded Assembly:
  text ".Layer_Name" at 577,-858.49 h60
M19 Embedded Keepout:
  text ".Layer_Name" at 577,-858.49 h60

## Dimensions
0,-400 to 1000,-400 on M2 Board Dimensions
0,0 to 0,1181.1 on M2 Board Dimensions
0,0 to 2755.91,0 on M2 Board Dimensions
